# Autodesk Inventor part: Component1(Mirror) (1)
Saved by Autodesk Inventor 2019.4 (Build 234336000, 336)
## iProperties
Created: 2020-06
Part Number: Component1(Mirror) (1)
Material: Generic
Document SubType Name: Modeling
Designer: Administrator
Density: 1 g/cm^3
Appearance: Default
Title: Component1(Mirror) (1)
Author: Administrator
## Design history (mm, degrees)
